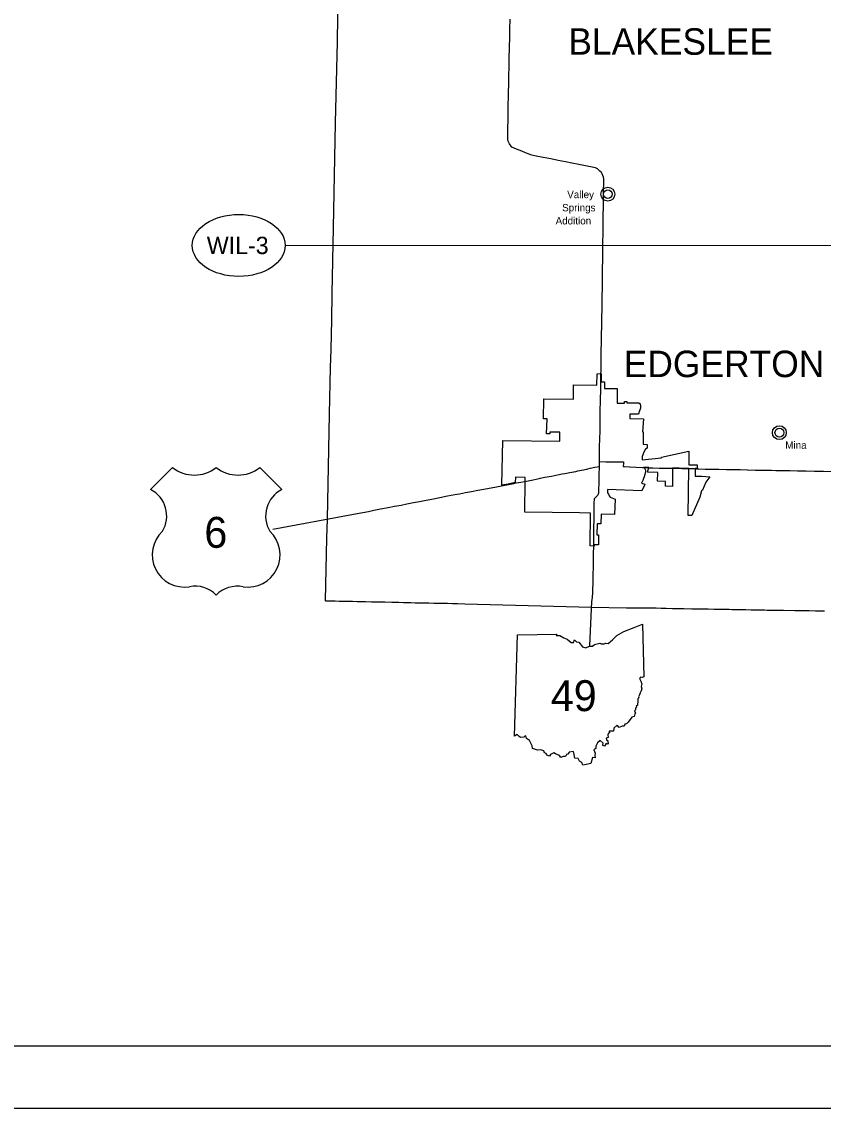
# Model space of a CAD drawing. Extents: x -66 to 795, y 0 to 440.
# Drawn here: x 111.4 to 240.8, y 0 to 175.4 of the extents above; entities that cross this region are included whole.
import ezdxf

# ---------------------------------------------------------------- set-up
doc = ezdxf.new("R2010")
doc.units = 0
for name, color, linetype in [('DV_X_Corp_Line', 7, 'Continuous'), ('GM_X_Corporation_Text', 7, 'Continuous'), ('GM_X_County', 7, 'Continuous'), ('GM_X_State_Route', 7, 'Continuous'), ('GM_X_US_Route', 7, 'Continuous'), ('PV_P_Text', 7, 'Continuous'), ('RD_P_Fence', 7, 'Continuous'), ('SH_Border', 7, 'Continuous'), ('SH_Cut_Line', 7, 'Continuous'), ('SH_Data', 7, 'Continuous')]:
    doc.layers.add(name, color=color, linetype=linetype)

msp = doc.modelspace()

# ---------------------------------------------------------------- linework, layer by layer
at = {"layer": 'DV_X_Corp_Line'}
msp.add_lwpolyline([(189.09, 107.8), (198.3, 107.69), (198.3, 109.13), (196.69, 109.14), (196.68, 108.86), (196.17, 108.86), (196.24, 111.29), (195.68, 111.3), (195.74, 114.5), (200.5, 114.47), (200.53, 116.77), (204.29, 116.73), (204.33, 118.55), (204.99, 118.6), (204.97, 117.92), (204.96, 117.27), (205.52, 117.26), (205.52, 116.21), (207.55, 116.19), (207.54, 113.84), (208.77, 113.81), (208.76, 114.09), (209.11, 114.09), (209.11, 113.89), (211.08, 113.89), (211.28, 113.7), (211.35, 113.36), (211.33, 113.01), (211.09, 112.4), (211.07, 112.31), (211.06, 112.24), (211.06, 112.2), (211.04, 112.15), (211.02, 112.06), (209.62, 112.07), (209.59, 111.36), (211.8, 111.3), (211.63, 109.19), (211.78, 109.17), (211.77, 108.29), (211.76, 107.21), (212.42, 107.14), (212.42, 106.54), (212.16, 106.41), (211.87, 105.92), (211.61, 105.19), (211.59, 104.89), (211.59, 104.65), (214.74, 104.97), (214.74, 105.12), (219.16, 106.07), (219.12, 103.85), (220.49, 103.86), (220.48, 103.26), (220.18, 103.27), (220.18, 102.04), (221.24, 102.04), (222.54, 101.93), (221.89, 101.06), (221.36, 99.75), (221.18, 99.66), (220.9, 98.63), (219.6, 95.7), (219, 95.71), (219.12, 103.29), (217.55, 103.31), (216.87, 103.33), (216.48, 103.33), (216.5, 100.37), (215.36, 100.4), (215.38, 101.19), (214.09, 101.21), (214.12, 102.64), (212.46, 102.68), (212.56, 103.06), (212.68, 103.44), (212.37, 103.46), (211.84, 103.5), (212, 103.3), (212.08, 103.12), (212.12, 102.92), (212.13, 102.77), (212.1, 102.58), (212.03, 102.28), (211.94, 101.93), (211.83, 101.67), (211.68, 101.34), (211.5, 100.93), (212.05, 100.75), (212, 100.56), (211.93, 100.4), (211.61, 99.84), (211.55, 99.66), (206, 99.88), (205.98, 99.75), (206, 99.51), (206.02, 99.33), (206.17, 99.11), (206.26, 98.87), (206.44, 98.66), (207.23, 98.3), (207.12, 95.85), (204.95, 95.89), (204.91, 94.34), (204.35, 94.34), (204.3, 92.58), (204.55, 92.57), (204.52, 90.95), (203.83, 90.94), (203.83, 90.75), (203.18, 90.79), (203.26, 96.06), (201.5, 96.1), (192.63, 96.21), (192.71, 101.3), (192.72, 101.84), (191.12, 101.85), (191.11, 100.99), (189.97, 100.77), (188.94, 100.58)], close=True, dxfattribs=at)
for centre, radius in [((206.05, 147.56), 1.12), ((206.05, 147.56), 0.71), ((233.76, 109.06), 1.12), ((233.76, 109.06), 0.71)]:
    msp.add_circle(centre, radius, dxfattribs=at)
at = {"layer": 'GM_X_County'}
msp.add_lwpolyline([(162.51, 184.25), (162.31, 172.16), (162.03, 159.05), (161.69, 142.12), (161.47, 131.5), (161.41, 127.27), (161.31, 122.46), (161.22, 119.56), (161.05, 112.02), (160.72, 95.1), (160.63, 92), (160.39, 81.94), (160.45, 81.93), (160.49, 81.93), (160.61, 81.92), (160.79, 81.92), (161.14, 81.91), (161.56, 81.9), (162.02, 81.89), (162.66, 81.88), (163.31, 81.87), (164.36, 81.85), (164.81, 81.84), (165.57, 81.82), (166.49, 81.8), (166.83, 81.79), (166.91, 81.78), (167.89, 81.76), (168.93, 81.74), (170.01, 81.73), (171.16, 81.7), (171.45, 81.69), (172.28, 81.67), (173.03, 81.65), (173.78, 81.64), (174.26, 81.63), (174.92, 81.61), (175.65, 81.6), (177.13, 81.57), (177.94, 81.55), (178.83, 81.53), (179.61, 81.52), (180.14, 81.51), (180.97, 81.49), (181.07, 81.49), (181.76, 81.48), (182.97, 81.44), (203.42, 80.91), (209.06, 80.77), (209.1, 80.79), (209.14, 80.79), (209.18, 80.8), (209.25, 80.79), (210.35, 80.79), (211.23, 80.79), (211.58, 80.78), (212.57, 80.77), (213.88, 80.76), (214.65, 80.75), (215.48, 80.73), (216.49, 80.7), (217.77, 80.68), (218.31, 80.67), (219.61, 80.64), (220.63, 80.62), (221.71, 80.61), (222.26, 80.6), (223.24, 80.59), (223.86, 80.58), (224.92, 80.56), (225.64, 80.54), (226.14, 80.53), (226.23, 80.53), (226.35, 80.53), (227.48, 80.51), (228.32, 80.5), (229.22, 80.48), (230.24, 80.46), (231.38, 80.44), (231.77, 80.43), (232.38, 80.42), (233.29, 80.41), (233.76, 80.39), (233.83, 80.39), (234.44, 80.38), (236.28, 80.35), (236.76, 80.35), (237.54, 80.34), (238.58, 80.33), (239.58, 80.32), (240.33, 80.3), (241.04, 80.29)], dxfattribs=at)
at = {"layer": 'GM_X_State_Route'}
for points in [[(204.94, 118.47), (204.94, 118.47), (204.95, 119.21), (204.96, 119.95), (204.98, 120.75), (205, 122.18), (205.02, 123.71), (205.04, 125.09), (205.08, 126.08), (205.09, 127.42), (205.12, 129.21), (205.15, 130.9), (205.17, 132.52), (205.2, 133.67), (205.21, 133.81), (205.21, 135.46), (205.23, 137), (205.25, 138.37), (205.26, 139.86), (205.28, 141.16), (205.28, 141.26), (205.31, 142.77), (205.32, 144.1), (205.33, 145.45), (205.35, 146.72), (205.37, 148.11), (205.38, 149.37), (205.4, 150.04), (205.35, 150.32), (205.26, 150.58), (205.14, 150.85), (205.01, 151.04), (204.77, 151.29), (204.51, 151.55), (204.38, 151.64), (204.27, 151.71), (204.05, 151.83), (203.54, 151.94), (202.44, 152.15), (201.38, 152.36), (200.26, 152.58), (199.23, 152.79), (198.04, 153.01), (196.83, 153.25), (195.63, 153.48), (194.49, 153.68), (193.97, 153.79), (193.78, 153.83), (193.58, 153.91), (193.33, 154.01), (192.78, 154.24), (192.16, 154.49), (191.28, 154.84), (190.56, 155.15), (190.42, 155.32), (190.27, 155.52), (190.17, 155.67), (190.07, 155.9), (189.96, 156.09), (189.91, 156.36), (189.91, 156.58), (189.92, 157.34), (189.92, 158.07), (189.93, 159.71), (189.95, 161), (189.98, 162.11), (189.99, 163.14), (190.02, 164.09), (190.04, 165.2), (190.07, 166.67), (190.1, 168.18), (190.14, 169.63), (190.17, 171.07), (190.18, 171.54), (190.2, 172.57), (190.23, 174.2), (190.28, 175.79)], [(204.92, 116.98), (204.92, 116.98), (204.93, 117.65), (204.94, 118.47)], [(204.87, 114.15), (204.87, 114.43), (204.9, 115.99), (204.92, 116.98)], [(204.82, 111.03), (204.83, 111.43), (204.84, 112.84), (204.86, 113.92), (204.87, 114.15)], [(204.73, 106.8), (204.73, 106.8), (204.77, 108), (204.77, 108.13), (204.79, 109.32), (204.8, 110.46), (204.82, 111.03)], [(204.7, 104.38), (204.72, 105.53), (204.72, 105.56), (204.73, 106.64), (204.73, 106.77), (204.73, 106.8)], [(204.67, 102.7), (204.68, 103.11), (204.69, 103.61)], [(203.89, 98.44), (203.89, 98.44), (204.22, 98.76), (204.43, 98.96), (204.5, 99.08), (204.56, 99.19), (204.59, 99.35), (204.6, 99.73), (204.61, 99.94), (204.63, 100.79), (204.65, 101.68), (204.66, 102.26), (204.67, 102.7)], [(203.85, 96.02), (203.85, 96.02), (203.85, 96.34), (203.87, 97.57), (203.89, 98.44)], [(203.78, 92.08), (203.78, 92.09), (203.78, 92.36), (203.8, 93.67), (203.83, 95.05), (203.85, 96.02)], [(203.77, 90.88), (203.77, 90.93), (203.78, 92.08)], [(203.13, 74.68), (203.46, 81.74), (203.51, 82.12), (203.56, 82.43), (203.6, 82.69), (203.63, 83.03), (203.65, 83.72), (203.66, 84.78), (203.69, 86.16), (203.71, 87.36), (203.73, 88.44), (203.74, 89.51), (203.77, 90.72)], [(203.77, 90.72), (203.77, 90.88)]]:
    msp.add_lwpolyline(points, dxfattribs=at)
at = {"layer": 'GM_X_US_Route'}
for points in [[(202.36, 103.12), (202.67, 103.18), (202.8, 103.21), (203.21, 103.3), (203.93, 103.47), (204.69, 103.61)], [(204.69, 103.61), (204.7, 104.38)], [(204.7, 104.38), (205.71, 104.36), (206.6, 104.35), (206.66, 104.35), (207.72, 104.34), (208.56, 104.33), (208.56, 104.16), (208.56, 104.16)], [(208.56, 104.16), (208.54, 103.61), (208.76, 103.6), (208.76, 103.6)], [(208.76, 103.6), (209.57, 103.56), (210.61, 103.5), (211.63, 103.46), (212.01, 103.44), (212.01, 103.44)], [(195.11, 101.69), (195.11, 101.69), (195.9, 101.85), (196.95, 102.05), (197.91, 102.23), (198.67, 102.39), (199.1, 102.47)], [(199.1, 102.47), (199.62, 102.57), (200.52, 102.75), (200.58, 102.76), (200.58, 102.76)], [(200.58, 102.76), (200.86, 102.81), (201.23, 102.89), (202.11, 103.07), (202.36, 103.12)], [(212.01, 103.44), (212.35, 103.42), (212.63, 103.4)], [(212.63, 103.4), (213.31, 103.37), (214.32, 103.35), (215.1, 103.31), (216.05, 103.3), (216.48, 103.3)], [(216.48, 103.3), (216.48, 103.3), (216.87, 103.3), (217.99, 103.28), (218.92, 103.28), (218.99, 103.28)], [(218.99, 103.28), (219.78, 103.26), (220.05, 103.25)], [(220.05, 103.25), (220.36, 103.24)], [(220.36, 103.24), (220.77, 103.23), (221.75, 103.19), (222.64, 103.18)], [(222.64, 103.18), (222.7, 103.18), (224, 103.14), (225.2, 103.13), (226.36, 103.12), (226.58, 103.11), (227.43, 103.1), (228.6, 103.07), (229.89, 103.03), (231.15, 103.02), (232.48, 102.98), (233.17, 102.97), (233.38, 102.97), (234.12, 102.94), (235.46, 102.93), (236.93, 102.9), (238.11, 102.88), (239.46, 102.86), (240.87, 102.83)], [(151.93, 93.5), (164.68, 95.83), (165.58, 96), (166.48, 96.18), (167.37, 96.35), (168.28, 96.54), (169.36, 96.74), (170.56, 96.97), (171.61, 97.17), (172.65, 97.38), (173.61, 97.56), (174.67, 97.77), (175.64, 97.95), (176.7, 98.17), (177.61, 98.34), (178.9, 98.6), (180.13, 98.84), (181.33, 99.07), (182.09, 99.21), (183.05, 99.4), (184.02, 99.58), (185.07, 99.78), (186, 99.95), (186.88, 100.11), (187.8, 100.28), (188.87, 100.49), (190.02, 100.7), (190.89, 100.87), (191.26, 100.94)], [(191.26, 100.94), (191.26, 100.94), (192.02, 101.08), (192.59, 101.19)], [(192.59, 101.19), (192.94, 101.25), (194.01, 101.47), (194.95, 101.65), (195.11, 101.69)]]:
    msp.add_lwpolyline(points, dxfattribs=at)
at = {"layer": 'PV_P_Text'}
for p, q in [((135.75, 103.43), (132.2, 99.89)), ((135.75, 103.43), (132.2, 99.89)), ((153.39, 99.89), (149.84, 103.43)), ((153.39, 99.89), (149.84, 103.43)), ((190.98, 60.06), (191.44, 76.43)), ((190.98, 60.06), (191.44, 76.43))]:
    msp.add_line(p, q, dxfattribs=at)
for points in [[(191.44, 76.43), (197.8, 76.54), (197.7, 76.34), (198.3, 76.3), (198.93, 75.95), (199.47, 75.73), (200.13, 75.21), (200.52, 75.21), (200.69, 75.64), (200.99, 75.31), (201.35, 75.25), (201.97, 74.47), (202.48, 74.3), (203.09, 74.57), (203.55, 74.61), (203.89, 74.88), (204.76, 75.1), (205, 74.97), (205.46, 74.99), (205.69, 75.09), (206.1, 75.01), (206.81, 75.6), (207.53, 76.3), (208.66, 76.96), (210.33, 77.59), (211.66, 78.15), (211.85, 69.66)], [(191.44, 76.43), (197.8, 76.54), (197.7, 76.34), (198.3, 76.3), (198.93, 75.95), (199.47, 75.73), (200.13, 75.21), (200.52, 75.21), (200.69, 75.64), (200.99, 75.31), (201.35, 75.25), (201.97, 74.47), (202.48, 74.3), (203.09, 74.57), (203.55, 74.61), (203.89, 74.88), (204.76, 75.1), (205, 74.97), (205.46, 74.99), (205.69, 75.09), (206.1, 75.01), (206.81, 75.6), (207.53, 76.3), (208.66, 76.96), (210.33, 77.59), (211.66, 78.15), (211.85, 69.66)], [(211.85, 69.66), (211.65, 69.54), (211.35, 69.59), (211.14, 69.35), (211.4, 68.96), (211.52, 68.54), (211.41, 68.07), (211.52, 67.69), (211.44, 67.37), (211.25, 67.05), (211.19, 66.75), (211.02, 66.43), (211.04, 66.25), (210.88, 66.11), (210.91, 65.58), (210.83, 65.29), (210.86, 65.03), (210.61, 64.96), (210.67, 64.75), (210.51, 64.59), (210.54, 64.31), (210.36, 64.14), (210.53, 63.78), (210.39, 63.67), (210.28, 63.23), (209.95, 63.14), (209.31, 62.35), (209.08, 62.05), (208.82, 61.98), (208.68, 61.67), (208.37, 61.67), (207.89, 61.46), (207.58, 61.82), (207.04, 61.38), (206.98, 60.87), (206.29, 60.89), (206.32, 60.63), (206.17, 60.55), (206.03, 60.29), (206.11, 59.83), (205.79, 59.72), (205.83, 59.45), (206.03, 59.29), (206.13, 58.78), (205.79, 58.88), (205.51, 58.45), (205.22, 58.55), (205.31, 58.92), (204.83, 59.35), (204.37, 59), (204.13, 58.44), (204.13, 58.07), (203.79, 57.84), (204.01, 57.31), (203.97, 56.94), (203.98, 56.59), (203.55, 56.6), (203.29, 55.66)], [(211.85, 69.66), (211.65, 69.54), (211.35, 69.59), (211.14, 69.35), (211.4, 68.96), (211.52, 68.54), (211.41, 68.07), (211.52, 67.69), (211.44, 67.37), (211.25, 67.05), (211.19, 66.75), (211.02, 66.43), (211.04, 66.25), (210.88, 66.11), (210.91, 65.58), (210.83, 65.29), (210.86, 65.03), (210.61, 64.96), (210.67, 64.75), (210.51, 64.59), (210.54, 64.31), (210.36, 64.14), (210.53, 63.78), (210.39, 63.67), (210.28, 63.23), (209.95, 63.14), (209.31, 62.35), (209.08, 62.05), (208.82, 61.98), (208.68, 61.67), (208.37, 61.67), (207.89, 61.46), (207.58, 61.82), (207.04, 61.38), (206.98, 60.87), (206.29, 60.89), (206.32, 60.63), (206.17, 60.55), (206.03, 60.29), (206.11, 59.83), (205.79, 59.72), (205.83, 59.45), (206.03, 59.29), (206.13, 58.78), (205.79, 58.88), (205.51, 58.45), (205.22, 58.55), (205.31, 58.92), (204.83, 59.35), (204.37, 59), (204.13, 58.44), (204.13, 58.07), (203.79, 57.84), (204.01, 57.31), (203.97, 56.94), (203.98, 56.59), (203.55, 56.6), (203.29, 55.66)], [(203.29, 55.66), (202.55, 55.48), (202.03, 55.38), (201.85, 55.8), (201.48, 56.03), (201.25, 56.46), (200.72, 56.52), (200.59, 57.11), (200.53, 57.59), (199.81, 57.47), (199.61, 57.17), (199.36, 57.1), (199.21, 56.8), (198.86, 56.78), (198.48, 56.64), (198.24, 56.93), (197.62, 57.22), (197.35, 57.37), (196.77, 57.13), (196.65, 56.86), (196.19, 56.98), (196.08, 57.29), (195.8, 57.38), (195.74, 57.71), (195.15, 57.88), (194.69, 57.81), (193.89, 58.07), (193.84, 58.5), (193.57, 59.02), (193.42, 59.39), (192.92, 59.67), (192.81, 60.1), (192.65, 60.08), (192.5, 59.91), (191.94, 59.83), (191.72, 60.01), (191.4, 60.31), (190.98, 60.06)], [(203.29, 55.66), (202.55, 55.48), (202.03, 55.38), (201.85, 55.8), (201.48, 56.03), (201.25, 56.46), (200.72, 56.52), (200.59, 57.11), (200.53, 57.59), (199.81, 57.47), (199.61, 57.17), (199.36, 57.1), (199.21, 56.8), (198.86, 56.78), (198.48, 56.64), (198.24, 56.93), (197.62, 57.22), (197.35, 57.37), (196.77, 57.13), (196.65, 56.86), (196.19, 56.98), (196.08, 57.29), (195.8, 57.38), (195.74, 57.71), (195.15, 57.88), (194.69, 57.81), (193.89, 58.07), (193.84, 58.5), (193.57, 59.02), (193.42, 59.39), (192.92, 59.67), (192.81, 60.1), (192.65, 60.08), (192.5, 59.91), (191.94, 59.83), (191.72, 60.01), (191.4, 60.31), (190.98, 60.06)]]:
    msp.add_lwpolyline(points, dxfattribs=at)
for centre, radius, start, end in [((139.27, 107.91), 5.7, 231.813, 308.187), ((139.27, 107.91), 5.7, 231.813, 308.187), ((146.32, 107.91), 5.7, 231.813, 308.187), ((146.32, 107.91), 5.7, 231.813, 308.187), ((129.99, 95.61), 4.82, 329.1175, 62.6108), ((129.99, 95.61), 4.82, 329.1175, 62.6108), ((155.6, 95.61), 4.82, 117.3892, 210.8825), ((155.6, 95.61), 4.82, 117.3892, 210.8825), ((137.67, 89.33), 5.2, 133.0046, 278.7282), ((137.67, 89.33), 5.2, 133.0046, 278.7282), ((147.92, 89.33), 5.2, 261.2718, 46.9954), ((147.92, 89.33), 5.2, 261.2718, 46.9954), ((139.42, 79.64), 4.65, 43.4177, 101.8742), ((139.42, 79.64), 4.65, 43.4177, 101.8742), ((146.27, 79.33), 4.94, 79.9613, 134.7468), ((146.27, 79.33), 4.94, 79.9613, 134.7468)]:
    msp.add_arc(centre, radius, start, end, dxfattribs=at)
at = {"layer": 'RD_P_Fence'}
msp.add_lwpolyline([(220.36, 103.24), (242.1, 102.81), (248.65, 102.7), (255.39, 101.38), (261.72, 98.29), (267.34, 96.11), (284.32, 94.68), (344.85, 93.53), (358.88, 93.36)], dxfattribs=at)
at = {"layer": 'SH_Border'}
msp.add_lwpolyline([(30, 430), (670, 430), (670, 10), (30, 10)], close=True, dxfattribs=at)
at = {"layer": 'SH_Cut_Line'}
msp.add_lwpolyline([(0, 0), (680, 0), (680, 440), (0, 440)], close=True, dxfattribs=at)
at = {"layer": 'SH_Data'}
msp.add_line((153.94, 139.28), (322.26, 139.35), dxfattribs=at)
msp.add_ellipse((146.44, 139.28), major_axis=(7.5, 0), ratio=0.666667, dxfattribs=at)

# ---------------------------------------------------------------- texts
at = {"layer": 'DV_X_Corp_Line'}
for s, p in [('Valley', (199.49, 146.91)), ('Springs', (198.67, 144.79)), ('Addition', (197.62, 142.67)), ('Mina', (234.71, 106.45))]:
    msp.add_text(s, height=1.188, rotation=0, dxfattribs=at).set_placement(p)
at = {"layer": 'GM_X_Corporation_Text'}
for s, p in [('BLAKESLEE', (199.67, 170.06)), ('EDGERTON', (208.62, 118.02))]:
    msp.add_text(s, height=4.275, rotation=0, dxfattribs=at).set_placement(p)
at = {"layer": 'PV_P_Text'}
for s, height, p in [('6', 4.99, (140.88, 90.47)), ('49', 4.987, (196.84, 64.11))]:
    msp.add_text(s, height=height, dxfattribs=at).set_placement(p)
at = {"layer": 'SH_Data'}
msp.add_text('WIL-3', height=2.8, dxfattribs=at).set_placement((141.28, 137.88))

doc.saveas('drawing.dxf')
